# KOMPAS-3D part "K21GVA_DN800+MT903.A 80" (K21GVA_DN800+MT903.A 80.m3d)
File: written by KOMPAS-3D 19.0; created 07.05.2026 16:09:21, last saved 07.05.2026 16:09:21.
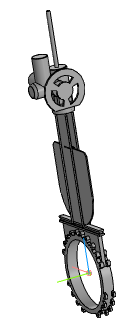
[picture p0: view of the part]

Document properties: Автор: Энергия; Полное имя файла: ..\K21GVA_DN50-DN1000+MT903.A\K21GVA_DN800+MT903.A 80.a3d

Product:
- Part/product: K21GVA_DN800+MT903.A 80
    Масса: 722.083

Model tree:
1. Операция без истории:1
